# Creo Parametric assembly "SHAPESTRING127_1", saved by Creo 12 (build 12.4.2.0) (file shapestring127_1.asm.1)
Units: Custom; MM, KILOGRAM, SECS

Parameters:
  PTC_WM_ITERATION = "0"
  PTC_WM_VERSION = "-.0"
  PTC_WM_LIFECYCLE_STATE = "In Work"
  PTC_WM_LIFECYCLE = "MO_CADDocument"
  PTC_WM_CREATED_BY = "Maximilian Roepper (Z0017RMS: MO)"
  PTC_WM_CREATED_ON = "18-Sep-26 11:36:42 AM"
  PTC_WM_MODIFIED_BY = "Maximilian Roepper (Z0017RMS: MO)"
  PTC_WM_MODIFIED_ON = "18-Sep-26 11:36:46 AM"
  PDMLINKNUMBER = "PDM000071454823"
  PTC_WM_NUMBER = "PDM000071454823"

Other parameters: WEIGHT, WEIGHT_FACTOR, WEIGHT_ADD, MC_ERRORS, SUPPLIER

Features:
  1. coordinate system
  2. imported feature
  3. component "SHAPESTRING071_1"
  4. component "SHAPESTRING124_1"
  5. component "SHAPESTRING125_1"
  6. component "SHAPESTRING126_1"

Other named items: DRW_VIEW_ORG, ROUGH-GROB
